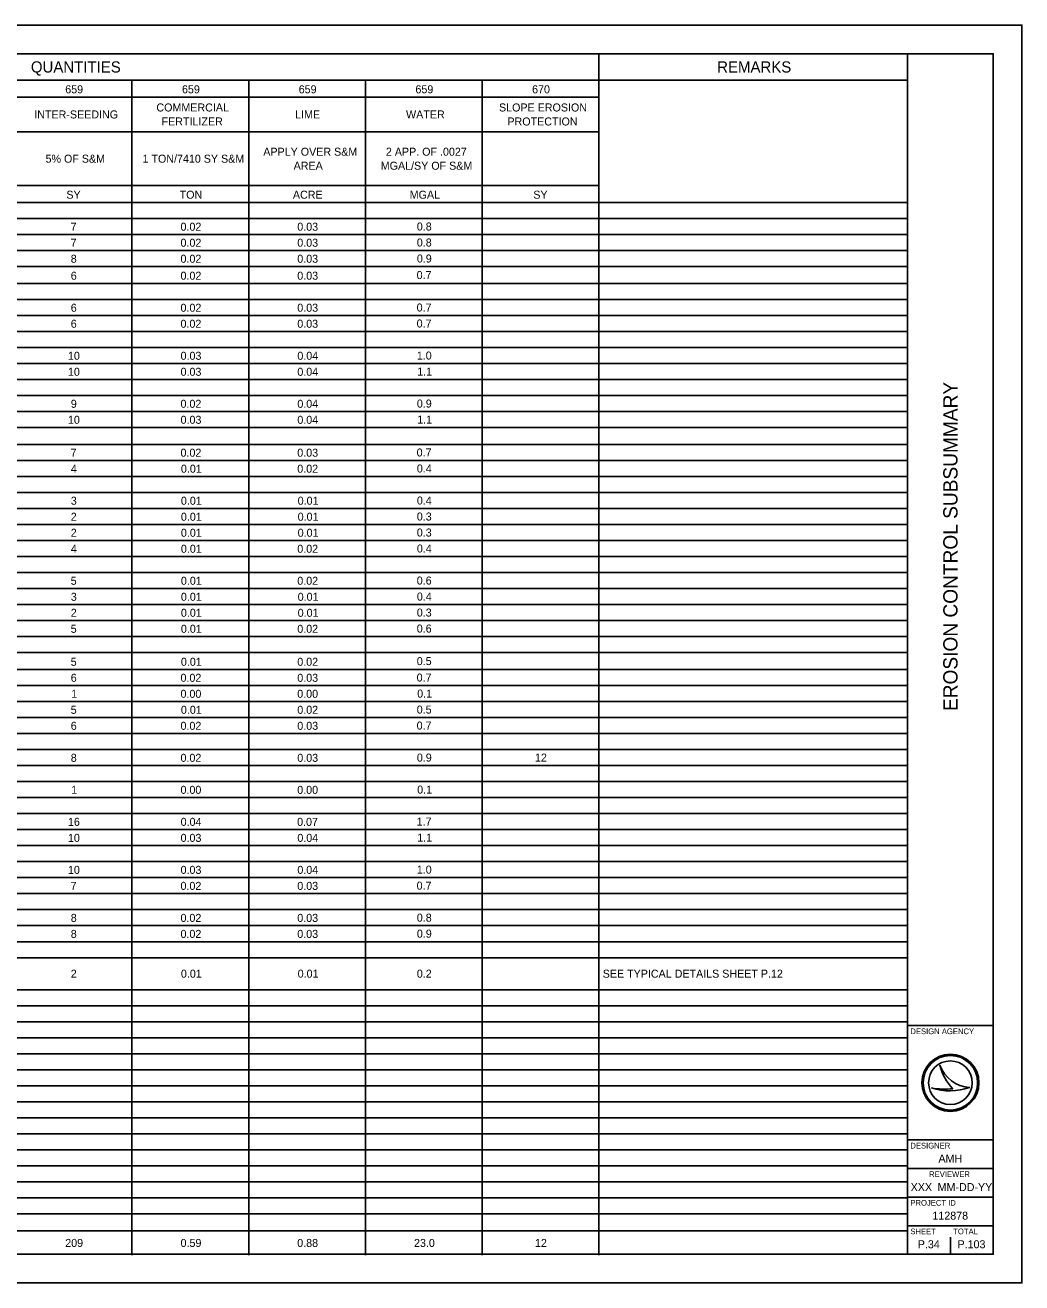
# Model space of a CAD drawing. Extents: x 0 to 34, y 0 to 22.
# Drawn here: x 16.56 to 34, y 0 to 22 of the extents above; entities that cross this region are included whole.
import ezdxf

# ---------------------------------------------------------------- set-up
doc = ezdxf.new("R2010")
doc.units = 0
for name, color, linetype in [('Default', 7, 'Continuous'), ('SH_Border', 7, 'Continuous'), ('SH_Cut_Line', 7, 'Continuous'), ('SH_Data', 7, 'Continuous')]:
    doc.layers.add(name, color=color, linetype=linetype)

msp = doc.modelspace()

# ---------------------------------------------------------------- linework, layer by layer
at = {"layer": 'Default'}
for p, q in [((1.5, 21.5), (31.987, 21.5)), ((26.601, 21.5), (26.601, 18.898)), ((1.5, 21.039), (31.987, 21.039)), ((18.432, 21.039), (18.432, 18.898)), ((20.474, 21.039), (20.474, 18.898)), ((22.516, 21.039), (22.516, 18.898)), ((24.559, 21.039), (24.559, 18.898)), ((10.262, 20.742), (26.601, 20.742)), ((10.262, 20.133), (26.601, 20.133)), ((7.561, 19.194), (26.601, 19.194)), ((1.5, 18.898), (26.601, 18.898)), ((18.432, 18.898), (18.432, 0.484)), ((20.474, 18.898), (20.474, 0.484)), ((22.516, 18.898), (22.516, 0.484)), ((24.559, 18.898), (24.559, 0.484)), ((26.601, 18.898), (31.987, 18.898)), ((26.601, 18.898), (26.601, 0.484)), ((1.5, 18.618), (31.987, 18.618)), ((1.5, 18.338), (31.987, 18.338)), ((1.5, 18.058), (31.987, 18.058)), ((1.5, 17.778), (31.987, 17.778)), ((1.5, 17.481), (31.987, 17.481)), ((1.5, 17.201), (31.987, 17.201)), ((1.5, 16.921), (31.987, 16.921)), ((1.5, 16.641), (31.987, 16.641)), ((1.5, 16.361), (31.987, 16.361)), ((1.5, 16.081), (31.987, 16.081)), ((1.5, 15.801), (31.987, 15.801)), ((1.5, 15.521), (31.987, 15.521)), ((1.5, 15.241), (31.987, 15.241)), ((1.5, 14.961), (31.987, 14.961)), ((1.5, 14.665), (31.987, 14.665)), ((1.5, 14.385), (31.987, 14.385)), ((1.5, 14.105), (31.987, 14.105)), ((1.5, 13.825), (31.987, 13.825)), ((1.5, 13.545), (31.987, 13.545)), ((1.5, 13.265), (31.987, 13.265)), ((1.5, 12.985), (31.987, 12.985)), ((1.5, 12.705), (31.987, 12.705)), ((1.5, 12.425), (31.987, 12.425)), ((1.5, 12.145), (31.987, 12.145)), ((1.5, 11.865), (31.987, 11.865)), ((1.5, 11.585), (31.987, 11.585)), ((1.5, 11.305), (31.987, 11.305)), ((1.5, 11.025), (31.987, 11.025)), ((1.5, 10.728), (31.987, 10.728)), ((1.5, 10.448), (31.987, 10.448)), ((1.5, 10.168), (31.987, 10.168)), ((1.5, 9.888), (31.987, 9.888)), ((1.5, 9.608), (31.987, 9.608)), ((1.5, 9.328), (31.987, 9.328)), ((1.5, 9.048), (31.987, 9.048)), ((1.5, 8.768), (31.987, 8.768)), ((1.5, 8.488), (31.987, 8.488)), ((1.5, 8.208), (31.987, 8.208)), ((1.5, 7.928), (31.987, 7.928)), ((1.5, 7.648), (31.987, 7.648)), ((1.5, 7.368), (31.987, 7.368)), ((1.5, 7.088), (31.987, 7.088)), ((1.5, 6.808), (31.987, 6.808)), ((1.5, 6.528), (31.987, 6.528)), ((1.5, 6.248), (31.987, 6.248)), ((1.5, 5.968), (31.987, 5.968)), ((1.5, 5.688), (31.987, 5.688)), ((1.5, 5.128), (31.987, 5.128)), ((1.5, 4.848), (31.987, 4.848)), ((1.5, 4.568), (31.987, 4.568)), ((1.5, 4.288), (31.987, 4.288)), ((1.5, 4.008), (31.987, 4.008)), ((1.5, 3.728), (31.987, 3.728)), ((1.5, 3.448), (31.987, 3.448)), ((1.5, 3.168), (31.987, 3.168)), ((1.5, 2.888), (31.987, 2.888)), ((1.5, 2.608), (31.987, 2.608)), ((1.5, 2.328), (31.987, 2.328)), ((1.5, 2.048), (31.987, 2.048)), ((1.5, 1.768), (31.987, 1.768)), ((1.5, 1.488), (31.987, 1.488)), ((1.5, 1.208), (31.987, 1.208)), ((1.5, 0.912), (31.987, 0.912))]:
    msp.add_line(p, q, dxfattribs=at)
at = {"layer": 'SH_Border'}
for p, q in [((32, 0.5), (32, 21.5)), ((32, 4.5), (33.5, 4.5)), ((32, 2.5), (33.5, 2.5)), ((32, 2), (33.5, 2)), ((32, 1.5), (33.5, 1.5)), ((32, 1), (33.5, 1))]:
    msp.add_line(p, q, dxfattribs=at)
msp.add_lwpolyline([(1.5, 21.5), (33.5, 21.5), (33.5, 0.5), (1.5, 0.5)], close=True, dxfattribs=at)
at = {"layer": 'SH_Cut_Line'}
msp.add_lwpolyline([(0, 0), (34, 0), (34, 22), (0, 22)], close=True, dxfattribs=at)
at = {"layer": 'SH_Data'}
for p, q in [((32.567, 3.81), (32.567, 3.81)), ((32.417, 3.41), (32.417, 3.41)), ((32.75, 3.5), (32.75, 3.5)), ((33.087, 3.419), (33.087, 3.419)), ((32.375, 0.675), (32.375, 0.675)), ((32.75, 0.5), (32.75, 0.8))]:
    msp.add_line(p, q, dxfattribs=at)
for radius in [0.5, 0.477, 0.477, 0.382]:
    msp.add_circle((32.75, 3.5), radius, dxfattribs=at)
for centre, radius, start, end in [((33.116, 3.998), 0.58, 198.9257, 198.9319), ((33.347, 3.97), 0.796, 191.6379, 191.6421), ((33.116, 3.998), 0.58, 198.9319, 267.1657), ((33.347, 3.97), 0.796, 191.6421, 226.0947), ((32.739, 4.37), 1.013, 251.4576, 290.0832), ((32.648, 4.654), 1.266, 259.4964, 259.4995), ((32.739, 4.37), 1.013, 251.4527, 251.4576), ((32.648, 4.654), 1.266, 259.4995, 276.6672)]:
    msp.add_arc(centre, radius, start, end, dxfattribs=at)

# ---------------------------------------------------------------- texts
at = {"layer": 'Default'}
for s, height, p in [('QUANTITIES', 0.196, (16.663, 21.171)), ('REMARKS', 0.196, (28.67, 21.171)), ('659', 0.14, (17.264, 20.808)), ('659', 0.14, (19.307, 20.808)), ('659', 0.14, (21.349, 20.808)), ('659', 0.14, (23.391, 20.808)), ('670', 0.14, (25.432, 20.808)), ('INTER-SEEDING', 0.14, (16.722, 20.368)), ('COMMERCIAL ', 0.14, (18.859, 20.49)), ('LIME', 0.14, (21.286, 20.368)), ('WATER', 0.14, (23.227, 20.368)), ('SLOPE EROSION ', 0.14, (24.853, 20.49)), ('FERTILIZER', 0.14, (18.95, 20.245)), ('PROTECTION', 0.14, (25, 20.245)), ('APPLY OVER S&M ', 0.14, (20.729, 19.716)), ('2 APP. OF .0027 ', 0.14, (22.874, 19.716)), ('5% OF S&M', 0.14, (16.92, 19.594)), ('1 TON/7410 SY S&M', 0.14, (18.616, 19.594)), ('AREA', 0.14, (21.26, 19.471)), ('MGAL/SY OF S&M', 0.14, (22.784, 19.471)), ('SY', 0.14, (17.284, 18.964)), ('TON', 0.14, (19.266, 18.964)), ('ACRE', 0.14, (21.247, 18.964)), ('MGAL', 0.14, (23.291, 18.964)), ('SY', 0.14, (25.453, 18.964)), ('7', 0.14, (17.358, 18.404)), ('0.02', 0.14, (19.281, 18.404)), ('0.03', 0.14, (21.324, 18.404)), ('0.8', 0.14, (23.415, 18.408)), ('7', 0.14, (17.358, 18.124)), ('0.02', 0.14, (19.281, 18.124)), ('0.03', 0.14, (21.324, 18.124)), ('0.8', 0.14, (23.415, 18.128)), ('8', 0.14, (17.361, 17.844)), ('0.02', 0.14, (19.281, 17.844)), ('0.03', 0.14, (21.324, 17.844)), ('0.9', 0.14, (23.416, 17.848)), ('6', 0.14, (17.361, 17.547)), ('0.02', 0.14, (19.281, 17.547)), ('0.03', 0.14, (21.324, 17.547)), ('0.7', 0.14, (23.412, 17.559)), ('6', 0.14, (17.361, 16.987)), ('0.02', 0.14, (19.281, 16.987)), ('0.03', 0.14, (21.324, 16.987)), ('0.7', 0.14, (23.412, 16.991)), ('6', 0.14, (17.361, 16.707)), ('0.02', 0.14, (19.281, 16.707)), ('0.03', 0.14, (21.324, 16.707)), ('0.7', 0.14, (23.412, 16.711)), ('10', 0.14, (17.312, 16.147)), ('0.03', 0.14, (19.282, 16.147)), ('0.04', 0.14, (21.325, 16.147)), ('1.0', 0.14, (23.415, 16.151)), ('10', 0.14, (17.312, 15.867)), ('0.03', 0.14, (19.282, 15.867)), ('0.04', 0.14, (21.325, 15.867)), ('1.1', 0.14, (23.422, 15.871)), ('9', 0.14, (17.362, 15.307)), ('0.02', 0.14, (19.281, 15.307)), ('0.04', 0.14, (21.325, 15.307)), ('0.9', 0.14, (23.416, 15.311)), ('10', 0.14, (17.312, 15.027)), ('0.03', 0.14, (19.282, 15.027)), ('0.04', 0.14, (21.325, 15.027)), ('1.1', 0.14, (23.422, 15.031)), ('7', 0.14, (17.358, 14.451)), ('0.02', 0.14, (19.281, 14.451)), ('0.03', 0.14, (21.324, 14.451)), ('0.7', 0.14, (23.412, 14.455)), ('4', 0.14, (17.363, 14.171)), ('0.01', 0.14, (19.288, 14.171)), ('0.02', 0.14, (21.324, 14.171)), ('0.4', 0.14, (23.416, 14.175)), ('3', 0.14, (17.362, 13.611)), ('0.01', 0.14, (19.288, 13.611)), ('0.01', 0.14, (21.331, 13.611)), ('0.4', 0.14, (23.416, 13.615)), ('2', 0.14, (17.361, 13.331)), ('0.01', 0.14, (19.288, 13.331)), ('0.01', 0.14, (21.331, 13.331)), ('0.3', 0.14, (23.415, 13.335)), ('2', 0.14, (17.361, 13.051)), ('0.01', 0.14, (19.288, 13.051)), ('0.01', 0.14, (21.331, 13.051)), ('0.3', 0.14, (23.415, 13.055)), ('4', 0.14, (17.363, 12.771)), ('0.01', 0.14, (19.288, 12.771)), ('0.02', 0.14, (21.324, 12.771)), ('0.4', 0.14, (23.416, 12.775)), ('5', 0.14, (17.36, 12.211)), ('0.01', 0.14, (19.288, 12.211)), ('0.02', 0.14, (21.324, 12.211)), ('0.6', 0.14, (23.414, 12.215)), ('3', 0.14, (17.362, 11.931)), ('0.01', 0.14, (19.288, 11.931)), ('0.01', 0.14, (21.331, 11.931)), ('0.4', 0.14, (23.416, 11.935)), ('2', 0.14, (17.361, 11.651)), ('0.01', 0.14, (19.288, 11.651)), ('0.01', 0.14, (21.331, 11.651)), ('0.3', 0.14, (23.415, 11.655)), ('5', 0.14, (17.36, 11.371)), ('0.01', 0.14, (19.288, 11.371)), ('0.02', 0.14, (21.324, 11.371)), ('0.6', 0.14, (23.414, 11.375)), ('5', 0.14, (17.36, 10.794)), ('0.01', 0.14, (19.288, 10.794)), ('0.02', 0.14, (21.324, 10.794)), ('0.5', 0.14, (23.414, 10.806)), ('6', 0.14, (17.361, 10.514)), ('0.02', 0.14, (19.281, 10.514)), ('0.03', 0.14, (21.324, 10.514)), ('0.7', 0.14, (23.412, 10.518)), ('1', 0.14, (17.368, 10.234)), ('0.00', 0.14, (19.281, 10.234)), ('0.00', 0.14, (21.323, 10.234)), ('0.1', 0.14, (23.422, 10.238)), ('5', 0.14, (17.36, 9.954)), ('0.01', 0.14, (19.288, 9.954)), ('0.02', 0.14, (21.324, 9.954)), ('0.5', 0.14, (23.414, 9.958)), ('6', 0.14, (17.361, 9.674)), ('0.02', 0.14, (19.281, 9.674)), ('0.03', 0.14, (21.324, 9.674)), ('0.7', 0.14, (23.412, 9.678)), ('8', 0.14, (17.361, 9.114)), ('0.02', 0.14, (19.281, 9.114)), ('0.03', 0.14, (21.324, 9.114)), ('0.9', 0.14, (23.416, 9.118)), ('12', 0.14, (25.482, 9.118)), ('1', 0.14, (17.368, 8.554)), ('0.00', 0.14, (19.281, 8.554)), ('0.00', 0.14, (21.323, 8.554)), ('0.1', 0.14, (23.422, 8.558)), ('16', 0.14, (17.312, 7.994)), ('0.04', 0.14, (19.283, 7.994)), ('0.07', 0.14, (21.321, 7.994)), ('1.7', 0.14, (23.412, 7.998)), ('10', 0.14, (17.312, 7.714)), ('0.03', 0.14, (19.282, 7.714)), ('0.04', 0.14, (21.325, 7.714)), ('1.1', 0.14, (23.422, 7.718)), ('10', 0.14, (17.312, 7.154)), ('0.03', 0.14, (19.282, 7.154)), ('0.04', 0.14, (21.325, 7.154)), ('1.0', 0.14, (23.415, 7.158)), ('7', 0.14, (17.358, 6.874)), ('0.02', 0.14, (19.281, 6.874)), ('0.03', 0.14, (21.324, 6.874)), ('0.7', 0.14, (23.412, 6.878)), ('8', 0.14, (17.361, 6.314)), ('0.02', 0.14, (19.281, 6.314)), ('0.03', 0.14, (21.324, 6.314)), ('0.8', 0.14, (23.415, 6.318)), ('8', 0.14, (17.361, 6.034)), ('0.02', 0.14, (19.281, 6.034)), ('0.03', 0.14, (21.324, 6.034)), ('0.9', 0.14, (23.416, 6.038)), ('2', 0.14, (17.361, 5.338)), ('0.01', 0.14, (19.288, 5.338)), ('0.01', 0.14, (21.331, 5.338)), ('0.2', 0.14, (23.415, 5.338)), ('SEE TYPICAL DETAILS SHEET P.12', 0.14, (26.667, 5.338)), ('209', 0.14, (17.264, 0.628)), ('0.59', 0.14, (19.282, 0.628)), ('0.88', 0.14, (21.323, 0.628)), ('23.0', 0.14, (23.366, 0.628)), ('12', 0.14, (25.482, 0.628))]:
    msp.add_text(s, height=height, dxfattribs=at).set_placement(p)
at = {"layer": 'SH_Data'}
msp.add_text('EROSION CONTROL SUBSUMMARY', height=0.25, rotation=90, dxfattribs=at).set_placement((32.875, 10.002))
for s, height, p in [('DESIGN AGENCY', 0.1, (32.05, 4.35)), ('DESIGNER', 0.1, (32.05, 2.35)), ('AMH', 0.14, (32.541, 2.105)), ('REVIEWER', 0.1, (32.378, 1.85)), ('XXX', 0.14, (32.055, 1.605)), ('MM-DD-YY', 0.14, (32.526, 1.605)), ('PROJECT ID', 0.1, (32.05, 1.35)), ('112878', 0.14, (32.435, 1.105)), ('SHEET', 0.1, (32.05, 0.85)), ('TOTAL', 0.1, (32.8, 0.85)), ('P.34', 0.14, (32.179, 0.605)), ('P.103', 0.14, (32.874, 0.605))]:
    msp.add_text(s, height=height, dxfattribs=at).set_placement(p)

doc.saveas('drawing.dxf')
